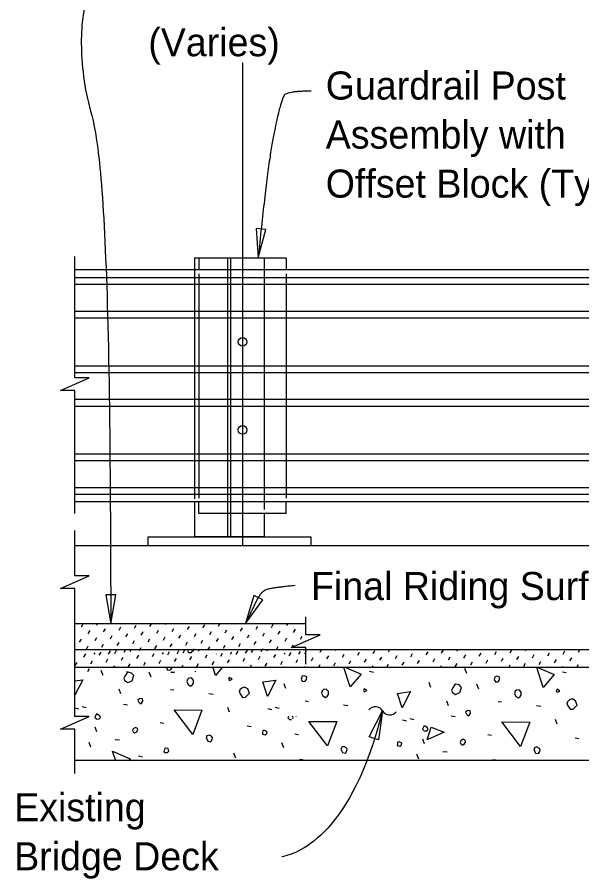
# Model space of a CAD drawing. Extents: x 21526.6 to 21598.7, y 56118.9 to 56155.9.
# Drawn here: x 21526.83 to 21530.88, y 56132.82 to 56139 of the extents above; entities that cross this region are included whole.
import ezdxf

# ---------------------------------------------------------------- set-up
doc = ezdxf.new("R2010")
doc.units = 0
for name, color, linetype in [('AdhocPoint_dp', 7, 'Continuous'), ('Border', 7, 'Continuous'), ('Patterning', 7, 'Continuous'), ('PlotBorder_dp', 7, 'Continuous'), ('SheetBorder_dp', 7, 'Continuous'), ('TextMisc', 7, 'Continuous')]:
    doc.layers.add(name, color=color, linetype=linetype)

msp = doc.modelspace()

# ---------------------------------------------------------------- linework, layer by layer
at = {"layer": 'AdhocPoint_dp'}
for p, q in [((21527.2426, 56135.21), (21535.6096, 56135.21)), ((21528.9006, 56134.6484), (21527.2426, 56134.6484)), ((21535.6096, 56134.46), (21527.2426, 56134.46)), ((21535.6096, 56134.335), (21527.2426, 56134.335)), ((21527.2426, 56133.6684), (21535.6096, 56133.6684))]:
    msp.add_line(p, q, dxfattribs=at)
at = {"layer": 'Patterning'}
for p, q in [((21528.4455, 56138.6758), (21528.4455, 56135.2123)), ((21528.758, 56137.2726), (21528.133, 56137.2726)), ((21528.133, 56137.2726), (21528.133, 56137.1892)), ((21528.758, 56137.2726), (21528.758, 56137.1892)), ((21528.133, 56137.1607), (21528.133, 56135.5488)), ((21528.758, 56137.1607), (21528.758, 56135.5488)), ((21527.2426, 56137.1336), (21534.2788, 56137.1336)), ((21527.2426, 56137.0854), (21534.2788, 56137.0854)), ((21527.2426, 56136.8926), (21534.2788, 56136.8926)), ((21527.2426, 56136.8444), (21534.2788, 56136.8444)), ((21527.2426, 56136.5004), (21534.2788, 56136.5004)), ((21527.2426, 56136.4522), (21534.2788, 56136.4522)), ((21527.2426, 56136.2594), (21534.2788, 56136.2594)), ((21527.2426, 56136.2112), (21534.2788, 56136.2112)), ((21527.2426, 56135.8673), (21534.2788, 56135.8673)), ((21527.2426, 56135.8191), (21534.2788, 56135.8191)), ((21527.2426, 56135.6262), (21534.2788, 56135.6262)), ((21527.2426, 56135.578), (21534.2788, 56135.578)), ((21528.133, 56135.4392), (21528.133, 56135.5226)), ((21528.758, 56135.4392), (21528.758, 56135.5226)), ((21528.758, 56135.4392), (21528.133, 56135.4392)), ((21527.2896, 56134.6259), (21527.3025, 56134.6483)), ((21527.4002, 56134.6388), (21527.4057, 56134.6484)), ((21527.449, 56134.59), (21527.462, 56134.6124)), ((21527.5597, 56134.603), (21527.5726, 56134.6254)), ((21527.6703, 56134.6159), (21527.6833, 56134.6383)), ((21527.7809, 56134.6289), (21527.7922, 56134.6484)), ((21527.8916, 56134.6419), (21527.8953, 56134.6484)), ((21527.9404, 56134.593), (21527.9534, 56134.6154)), ((21528.051, 56134.606), (21528.064, 56134.6284)), ((21528.1617, 56134.619), (21528.1746, 56134.6413)), ((21528.2723, 56134.6319), (21528.2818, 56134.6484)), ((21528.3829, 56134.6449), (21528.3849, 56134.6484)), ((21528.4318, 56134.596), (21528.4447, 56134.6184)), ((21528.5424, 56134.609), (21528.5553, 56134.6314)), ((21528.653, 56134.622), (21528.666, 56134.6444)), ((21528.7637, 56134.6349), (21528.7714, 56134.6484)), ((21528.8125, 56134.5861), (21528.8254, 56134.6085)), ((21528.8743, 56134.6479), (21528.8745, 56134.6484)), ((21527.3384, 56134.577), (21527.3514, 56134.5994)), ((21527.3872, 56134.5282), (21527.4002, 56134.5506)), ((21527.4979, 56134.5412), (21527.5108, 56134.5636)), ((21527.6085, 56134.5541), (21527.6215, 56134.5765)), ((21527.7191, 56134.5671), (21527.7321, 56134.5895)), ((21527.8298, 56134.5801), (21527.8427, 56134.6025)), ((21527.8786, 56134.5312), (21527.8916, 56134.5536)), ((21527.9892, 56134.5442), (21528.0022, 56134.5666)), ((21528.0999, 56134.5572), (21528.1128, 56134.5795)), ((21528.2105, 56134.5701), (21528.2235, 56134.5925)), ((21528.3211, 56134.5831), (21528.3341, 56134.6055)), ((21528.37, 56134.5342), (21528.3829, 56134.5566)), ((21528.4806, 56134.5472), (21528.4936, 56134.5696)), ((21528.5912, 56134.5602), (21528.6042, 56134.5826)), ((21528.7019, 56134.5731), (21528.7148, 56134.5955)), ((21528.7507, 56134.5243), (21528.7637, 56134.5467)), ((21528.8613, 56134.5373), (21528.8743, 56134.5597)), ((21527.2766, 56134.5152), (21527.2896, 56134.5376)), ((21527.3254, 56134.4664), (21527.3384, 56134.4888)), ((21527.4361, 56134.4794), (21527.449, 56134.5018)), ((21527.5467, 56134.4923), (21527.5597, 56134.5147)), ((21527.6573, 56134.5053), (21527.6703, 56134.5277)), ((21527.768, 56134.5183), (21527.7809, 56134.5407)), ((21527.8168, 56134.4694), (21527.8298, 56134.4918)), ((21527.9274, 56134.4824), (21527.9404, 56134.5048)), ((21528.0381, 56134.4954), (21528.051, 56134.5177)), ((21528.1487, 56134.5083), (21528.1617, 56134.5307)), ((21528.2593, 56134.5213), (21528.2723, 56134.5437)), ((21528.3082, 56134.4724), (21528.3211, 56134.4948)), ((21528.4188, 56134.4854), (21528.4318, 56134.5078)), ((21528.5294, 56134.4984), (21528.5424, 56134.5208)), ((21528.6401, 56134.5113), (21528.653, 56134.5337)), ((21528.6889, 56134.4625), (21528.7019, 56134.4849)), ((21528.7995, 56134.4755), (21528.8125, 56134.4979)), ((21528.9102, 56134.4884), (21528.9103, 56134.4886)), ((21527.2583, 56134.4585), (21527.2592, 56134.46)), ((21527.3071, 56134.4097), (21527.3201, 56134.4321)), ((21527.3811, 56134.4294), (21527.3872, 56134.44)), ((21527.4178, 56134.4226), (21527.4307, 56134.445)), ((21527.4849, 56134.4305), (21527.4979, 56134.4529)), ((21527.5284, 56134.4356), (21527.5413, 56134.458)), ((21527.5955, 56134.4435), (21527.6085, 56134.4659)), ((21527.639, 56134.4486), (21527.6457, 56134.46)), ((21527.6879, 56134.3997), (21527.7008, 56134.4221)), ((21527.7062, 56134.4565), (21527.7191, 56134.4789)), ((21527.7676, 56134.4294), (21527.768, 56134.43)), ((21527.7985, 56134.4127), (21527.8114, 56134.4351)), ((21527.8707, 56134.4294), (21527.8786, 56134.443)), ((21527.9091, 56134.4257), (21527.9221, 56134.4481)), ((21527.9763, 56134.4336), (21527.9892, 56134.4559)), ((21528.0198, 56134.4386), (21528.0321, 56134.46)), ((21528.0869, 56134.4465), (21528.0999, 56134.4689)), ((21528.1304, 56134.4516), (21528.1353, 56134.46)), ((21528.1792, 56134.4028), (21528.1922, 56134.4251)), ((21528.1975, 56134.4595), (21528.2105, 56134.4819)), ((21528.2572, 56134.4294), (21528.2593, 56134.433)), ((21528.2899, 56134.4157), (21528.3028, 56134.4381)), ((21528.3603, 56134.4294), (21528.37, 56134.446)), ((21528.4005, 56134.4287), (21528.4134, 56134.4511)), ((21528.4676, 56134.4366), (21528.4806, 56134.459)), ((21528.5111, 56134.4416), (21528.5218, 56134.46)), ((21528.5783, 56134.4495), (21528.5912, 56134.4719)), ((21528.6217, 56134.4546), (21528.6249, 56134.46)), ((21528.6706, 56134.4058), (21528.6835, 56134.4282)), ((21528.7468, 56134.4294), (21528.7507, 56134.4361)), ((21528.7812, 56134.4187), (21528.7942, 56134.4411)), ((21528.8499, 56134.4294), (21528.8613, 56134.449)), ((21528.8918, 56134.4317), (21528.9048, 56134.4541)), ((21529.0025, 56134.4447), (21529.0114, 56134.46)), ((21529.1131, 56134.4576), (21529.1145, 56134.46)), ((21529.1619, 56134.4088), (21529.1749, 56134.4312)), ((21529.2726, 56134.4218), (21529.2855, 56134.4441)), ((21529.3832, 56134.4347), (21529.3962, 56134.4571)), ((21529.4938, 56134.4477), (21529.501, 56134.46)), ((21529.6533, 56134.4118), (21529.6663, 56134.4342)), ((21529.7639, 56134.4248), (21529.7769, 56134.4472)), ((21529.8746, 56134.4377), (21529.8875, 56134.46)), ((21529.9852, 56134.4507), (21529.9906, 56134.46)), ((21530.034, 56134.4019), (21530.047, 56134.4243)), ((21530.1447, 56134.4148), (21530.1576, 56134.4372)), ((21530.2553, 56134.4278), (21530.2683, 56134.4502)), ((21530.3659, 56134.4408), (21530.3771, 56134.46)), ((21530.4766, 56134.4537), (21530.4802, 56134.46)), ((21530.5254, 56134.4049), (21530.5384, 56134.4273)), ((21530.636, 56134.4179), (21530.649, 56134.4402)), ((21530.7467, 56134.4308), (21530.7596, 56134.4532)), ((21530.8573, 56134.4438), (21530.8667, 56134.46)), ((21527.2453, 56134.3479), (21527.2583, 56134.3703)), ((21527.356, 56134.3608), (21527.3689, 56134.3832)), ((21527.4666, 56134.3738), (21527.4796, 56134.3962)), ((21527.5772, 56134.3868), (21527.5902, 56134.4092)), ((21527.6261, 56134.3379), (21527.639, 56134.3603)), ((21527.7367, 56134.3509), (21527.7497, 56134.3733)), ((21527.8473, 56134.3639), (21527.8603, 56134.3863)), ((21527.958, 56134.3768), (21527.9709, 56134.3992)), ((21528.0686, 56134.3898), (21528.0815, 56134.4122)), ((21528.1174, 56134.341), (21528.1304, 56134.3633)), ((21528.2281, 56134.3539), (21528.241, 56134.3763)), ((21528.3387, 56134.3669), (21528.3516, 56134.3893)), ((21528.4493, 56134.3798), (21528.4623, 56134.4022)), ((21528.56, 56134.3928), (21528.5729, 56134.4152)), ((21528.6088, 56134.344), (21528.6217, 56134.3664)), ((21528.7194, 56134.3569), (21528.7324, 56134.3793)), ((21528.8301, 56134.3699), (21528.843, 56134.3923)), ((21528.9407, 56134.3829), (21528.9536, 56134.4053)), ((21529.0513, 56134.3958), (21529.0643, 56134.4182)), ((21529.1002, 56134.347), (21529.1131, 56134.3694)), ((21529.2108, 56134.36), (21529.2237, 56134.3824)), ((21529.3214, 56134.3729), (21529.3344, 56134.3953)), ((21529.432, 56134.3859), (21529.445, 56134.4083)), ((21529.5427, 56134.3989), (21529.5556, 56134.4212)), ((21529.5915, 56134.35), (21529.6045, 56134.3724)), ((21529.7021, 56134.363), (21529.7151, 56134.3854)), ((21529.8128, 56134.3759), (21529.8257, 56134.3983)), ((21529.9234, 56134.3889), (21529.9364, 56134.4113)), ((21529.9722, 56134.3401), (21529.9852, 56134.3625)), ((21530.0829, 56134.353), (21530.0958, 56134.3754)), ((21530.1935, 56134.366), (21530.2065, 56134.3884)), ((21530.3041, 56134.379), (21530.3171, 56134.4014)), ((21530.4148, 56134.3919), (21530.4277, 56134.4143)), ((21530.4636, 56134.3431), (21530.4766, 56134.3655)), ((21530.5742, 56134.3561), (21530.5872, 56134.3784)), ((21530.6849, 56134.369), (21530.6978, 56134.3914)), ((21530.7955, 56134.382), (21530.8085, 56134.4044)), ((21527.3349, 56134.3055), (21527.3478, 56134.3279)), ((21527.4465, 56134.2767), (21527.4324, 56134.3121)), ((21527.5212, 56134.335), (21527.5284, 56134.3474)), ((21527.6176, 56134.3044), (21527.6179, 56134.305)), ((21527.7906, 56134.265), (21527.7765, 56134.3003)), ((21527.9077, 56134.335), (21527.9091, 56134.3374)), ((21528.0109, 56134.335), (21528.0198, 56134.3504)), ((21528.1072, 56134.3044), (21528.1093, 56134.308)), ((21528.3974, 56134.335), (21528.4005, 56134.3404)), ((21528.5005, 56134.335), (21528.5111, 56134.3534)), ((21528.887, 56134.335), (21528.8918, 56134.3435)), ((21528.9901, 56134.335), (21529.0025, 56134.3564)), ((21529.3562, 56134.3079), (21529.3845, 56134.3008)), ((21529.3766, 56134.335), (21529.3832, 56134.3465)), ((21529.4809, 56134.3371), (21529.4938, 56134.3594)), ((21529.7631, 56134.335), (21529.7639, 56134.3365)), ((21529.8662, 56134.335), (21529.8746, 56134.3495)), ((21530.0545, 56134.292), (21530.0403, 56134.3273)), ((21530.2527, 56134.335), (21530.2553, 56134.3396)), ((21530.3558, 56134.335), (21530.3659, 56134.3525)), ((21530.7409, 56134.3043), (21530.7691, 56134.2973)), ((21530.7423, 56134.335), (21530.7467, 56134.3426)), ((21530.8454, 56134.335), (21530.8573, 56134.3555)), ((21527.572, 56134.1442), (21527.5597, 56134.1777)), ((21527.9285, 56134.1766), (21527.9533, 56134.1731)), ((21528.7575, 56134.183), (21528.7434, 56134.2183)), ((21529.7981, 56134.1912), (21529.784, 56134.2266)), ((21530.1422, 56134.1795), (21530.1281, 56134.2148)), ((21528.2043, 56134.1483), (21528.2343, 56134.143)), ((21527.2945, 56134.054), (21527.3228, 56134.0469)), ((21527.5909, 56134.0723), (21527.6209, 56134.067)), ((21528.8954, 56134.0946), (21528.9202, 56134.0911)), ((21529.1712, 56134.0663), (21529.2012, 56134.061)), ((21529.9236, 56134.0586), (21529.9113, 56134.0922)), ((21530.2801, 56134.0911), (21530.3049, 56134.0875)), ((21530.5559, 56134.0628), (21530.5859, 56134.0575)), ((21527.2421, 56134.044), (21527.2704, 56134.037)), ((21528.3528, 56134.014), (21528.3404, 56134.0476)), ((21528.6268, 56134.0405), (21528.6551, 56134.0334)), ((21528.6792, 56134.0505), (21528.7075, 56134.0434)), ((21527.8543, 56133.9397), (21527.8808, 56133.9344)), ((21529.5937, 56133.9585), (21529.622, 56133.9514)), ((21529.6461, 56133.9685), (21529.6744, 56133.9614)), ((21529.9425, 56133.9868), (21529.9725, 56133.9815)), ((21530.7044, 56133.9284), (21530.692, 56133.962)), ((21527.4006, 56133.8714), (21527.3882, 56133.905)), ((21528.48, 56133.915), (21528.5066, 56133.9097)), ((21527.5308, 56133.8177), (21527.5626, 56133.8142)), ((21528.8212, 56133.8577), (21528.8477, 56133.8524)), ((21529.7522, 56133.7859), (21529.7398, 56133.8195)), ((21530.2059, 56133.8542), (21530.2324, 56133.8489)), ((21530.8316, 56133.8294), (21530.8582, 56133.8241)), ((21527.3581, 56133.7618), (21527.344, 56133.7972)), ((21528.7428, 56133.7583), (21528.7287, 56133.7936)), ((21527.6987, 56133.6993), (21527.727, 56133.6922)), ((21528.397, 56133.6834), (21528.3828, 56133.7188)), ((21529.7097, 56133.6763), (21529.6956, 56133.7116)), ((21529.8824, 56133.7322), (21529.9142, 56133.7287))]:
    msp.add_line(p, q, dxfattribs=at)
for points in [[(21528.0505, 56134.4567), (21528.0591, 56134.4413), (21528.0785, 56134.443), (21528.0874, 56134.4554), (21528.0875, 56134.4567)], [(21527.6003, 56134.2396), (21527.6233, 56134.2272), (21527.6534, 56134.2396), (21527.6657, 56134.2767), (21527.6481, 56134.2944), (21527.6251, 56134.2997), (21527.6145, 56134.2927), (21527.6021, 56134.2732), (21527.5933, 56134.2573), (21527.6003, 56134.2396)], [(21527.9005, 56134.3317), (21527.9091, 56134.3163), (21527.9285, 56134.318), (21527.9373, 56134.3304), (21527.9375, 56134.3317)], [(21527.9326, 56134.3044), (21527.9336, 56134.302), (21527.9312, 56134.3044)], [(21527.9336, 56134.302), (21527.9548, 56134.302), (21527.9572, 56134.3044)], [(21528.252, 56134.2774), (21528.2343, 56134.3317)], [(21528.298, 56134.3317), (21528.252, 56134.2774)], [(21529.2189, 56134.1954), (21529.1735, 56134.335)], [(21529.1874, 56134.335), (21529.2967, 56134.2873), (21529.2189, 56134.1954)], [(21530.6036, 56134.1918), (21530.557, 56134.335)], [(21530.564, 56134.335), (21530.6814, 56134.2838), (21530.6036, 56134.1918)], [(21527.2426, 56134.2391), (21527.2998, 56134.2467), (21527.2427, 56134.1358)], [(21528.0452, 56134.2332), (21528.0558, 56134.212), (21528.0735, 56134.2014), (21528.0876, 56134.212), (21528.0947, 56134.2226), (21528.0947, 56134.2438), (21528.0788, 56134.2597), (21528.0593, 56134.2579), (21528.0505, 56134.2491), (21528.0452, 56134.2332)], [(21528.351, 56134.242), (21528.3704, 56134.2509), (21528.3634, 56134.2579), (21528.351, 56134.2632), (21528.3457, 56134.2509), (21528.351, 56134.242)], [(21528.6244, 56134.1265), (21528.5908, 56134.2308), (21528.6845, 56134.2432), (21528.6244, 56134.1265)], [(21528.8671, 56134.2502), (21528.876, 56134.2343), (21528.8954, 56134.236), (21528.9043, 56134.2484), (21528.906, 56134.2678), (21528.8937, 56134.2731), (21528.8848, 56134.2749), (21528.8742, 56134.2714), (21528.8707, 56134.2678), (21528.8671, 56134.2502)], [(21530.2518, 56134.2466), (21530.2607, 56134.2307), (21530.2801, 56134.2325), (21530.2889, 56134.2449), (21530.2907, 56134.2643), (21530.2783, 56134.2696), (21530.2695, 56134.2714), (21530.2589, 56134.2678), (21530.2554, 56134.2643), (21530.2518, 56134.2466)], [(21528.4217, 56134.1572), (21528.4447, 56134.12), (21528.4677, 56134.1218), (21528.4765, 56134.1306), (21528.496, 56134.1501), (21528.4836, 56134.1801), (21528.4588, 56134.1943), (21528.4412, 56134.1872), (21528.427, 56134.1731), (21528.4217, 56134.1572)], [(21529.0121, 56134.1512), (21529.0227, 56134.13), (21529.0404, 56134.1194), (21529.0545, 56134.13), (21529.0616, 56134.1406), (21529.0616, 56134.1618), (21529.0457, 56134.1777), (21529.0262, 56134.1759), (21529.0174, 56134.1671), (21529.0121, 56134.1512)], [(21529.3179, 56134.16), (21529.3374, 56134.1689), (21529.3303, 56134.1759), (21529.3179, 56134.1812), (21529.3126, 56134.1689), (21529.3179, 56134.16)], [(21529.9519, 56134.1541), (21529.9749, 56134.1417), (21530.005, 56134.1541), (21530.0173, 56134.1912), (21529.9997, 56134.2089), (21529.9767, 56134.2142), (21529.9661, 56134.2071), (21529.9537, 56134.1877), (21529.9449, 56134.1718), (21529.9519, 56134.1541)], [(21530.7026, 56134.1565), (21530.722, 56134.1653), (21530.715, 56134.1724), (21530.7026, 56134.1777), (21530.6973, 56134.1653), (21530.7026, 56134.1565)], [(21529.5913, 56134.0445), (21529.5577, 56134.1488), (21529.6514, 56134.1612), (21529.5913, 56134.0445)], [(21530.3968, 56134.1476), (21530.4074, 56134.1264), (21530.4251, 56134.1158), (21530.4392, 56134.1264), (21530.4463, 56134.137), (21530.4463, 56134.1582), (21530.4304, 56134.1742), (21530.4109, 56134.1724), (21530.4021, 56134.1635), (21530.3968, 56134.1476)], [(21527.7022, 56134.0847), (21527.7128, 56134.0741), (21527.7234, 56134.0811), (21527.7305, 56134.0918), (21527.727, 56134.1094), (21527.7181, 56134.1112), (21527.7058, 56134.1094), (21527.6952, 56134.0988), (21527.7022, 56134.0847)], [(21530.7733, 56134.0716), (21530.7963, 56134.0345), (21530.8193, 56134.0363), (21530.8281, 56134.0451), (21530.8476, 56134.0646), (21530.8352, 56134.0946), (21530.8104, 56134.1087), (21530.7928, 56134.1017), (21530.7786, 56134.0875), (21530.7733, 56134.0716)], [(21527.397, 56133.9656), (21527.4094, 56133.9638), (21527.4218, 56133.9692), (21527.4253, 56133.9798), (21527.42, 56133.9886), (21527.4094, 56133.9957), (21527.397, 56134.001), (21527.39, 56133.9868), (21527.3864, 56133.9762), (21527.397, 56133.9656)], [(21528.0894, 56133.8531), (21527.955, 56134.0299), (21528.1548, 56134.0281), (21528.0894, 56133.8531)], [(21530.0538, 56133.9991), (21530.0644, 56133.9885), (21530.075, 56133.9956), (21530.0821, 56134.0062), (21530.0786, 56134.0239), (21530.0697, 56134.0257), (21530.0574, 56134.0239), (21530.0468, 56134.0133), (21530.0538, 56133.9991)], [(21528.776, 56133.9861), (21528.7746, 56133.9833), (21528.7711, 56133.9727), (21528.7817, 56133.9621)], [(21528.7817, 56133.9621), (21528.7941, 56133.9603), (21528.796, 56133.9611)], [(21528.8073, 56133.9681), (21528.81, 56133.9762), (21528.8047, 56133.9851), (21528.8031, 56133.9861)], [(21528.8302, 56133.9823), (21528.8314, 56133.9861)], [(21529.0563, 56133.7711), (21528.9219, 56133.9479), (21529.1217, 56133.9461), (21529.0563, 56133.7711)], [(21530.441, 56133.7676), (21530.3066, 56133.9443), (21530.5064, 56133.9426), (21530.441, 56133.7676)], [(21527.6669, 56133.8655), (21527.6739, 56133.8655), (21527.6881, 56133.8725), (21527.6934, 56133.8885), (21527.6916, 56133.8973), (21527.6775, 56133.9044), (21527.6598, 56133.8938), (21527.6563, 56133.8832), (21527.6598, 56133.8725), (21527.6669, 56133.8655)], [(21528.5879, 56133.8566), (21528.6073, 56133.8513), (21528.6197, 56133.8602), (21528.6215, 56133.8725), (21528.6179, 56133.8761), (21528.6038, 56133.8832), (21528.5914, 56133.8814), (21528.5897, 56133.869), (21528.5879, 56133.8566)], [(21529.7486, 56133.8801), (21529.761, 56133.8783), (21529.7734, 56133.8836), (21529.7769, 56133.8942), (21529.7716, 56133.9031), (21529.761, 56133.9101), (21529.7486, 56133.9154), (21529.7416, 56133.9013), (21529.738, 56133.8907), (21529.7486, 56133.8801)], [(21529.771, 56133.8153), (21529.7993, 56133.9072), (21529.893, 56133.8701), (21529.771, 56133.8153)], [(21528.1884, 56133.8213), (21528.1972, 56133.8054), (21528.2184, 56133.8018), (21528.2273, 56133.8177), (21528.2308, 56133.8319), (21528.222, 56133.8407), (21528.206, 56133.8496), (21528.1901, 56133.8443), (21528.1848, 56133.8284), (21528.1884, 56133.8213)], [(21530.0185, 56133.7799), (21530.0255, 56133.7799), (21530.0397, 56133.787), (21530.045, 56133.8029), (21530.0432, 56133.8118), (21530.0291, 56133.8188), (21530.0114, 56133.8082), (21530.0079, 56133.7976), (21530.0114, 56133.787), (21530.0185, 56133.7799)], [(21527.8861, 56133.7241), (21527.9073, 56133.7241), (21527.9179, 56133.7347), (21527.9126, 56133.7541), (21527.8896, 56133.7559), (21527.8861, 56133.7453), (21527.8808, 56133.7364), (21527.8861, 56133.7241), (21527.8825, 56133.7276)], [(21529.1553, 56133.7393), (21529.1641, 56133.7234), (21529.1853, 56133.7198), (21529.1942, 56133.7357), (21529.1977, 56133.7499), (21529.1889, 56133.7587), (21529.173, 56133.7676), (21529.1571, 56133.7623), (21529.1518, 56133.7464), (21529.1553, 56133.7393)], [(21529.5548, 56133.7746), (21529.5742, 56133.7693), (21529.5866, 56133.7782), (21529.5884, 56133.7905), (21529.5849, 56133.7941), (21529.5707, 56133.8012), (21529.5583, 56133.7994), (21529.5566, 56133.787), (21529.5548, 56133.7746)], [(21530.54, 56133.7357), (21530.5488, 56133.7198), (21530.57, 56133.7163), (21530.5789, 56133.7322), (21530.5824, 56133.7464), (21530.5736, 56133.7552), (21530.5576, 56133.764), (21530.5417, 56133.7587), (21530.5364, 56133.7428), (21530.54, 56133.7357)], [(21527.536, 56133.665), (21527.5137, 56133.7335), (21527.6392, 56133.6787), (21527.6276, 56133.665)], [(21528.8805, 56133.6684), (21528.8795, 56133.6721), (21528.8565, 56133.6739), (21528.8547, 56133.6684)], [(21530.2643, 56133.6684), (21530.2642, 56133.6686), (21530.2412, 56133.6703), (21530.2406, 56133.6684)]]:
    msp.add_lwpolyline(points, dxfattribs=at)
at = {"layer": 'PlotBorder_dp'}
for points in [[(21528.5583, 56137.2748), (21528.614, 56137.4786), (21528.5438, 56137.4856)], [(21527.5005, 56134.6471), (21527.5357, 56134.8553), (21527.4652, 56134.8553)], [(21528.466, 56134.6497), (21528.5907, 56134.8202), (21528.5275, 56134.8517)], [(21529.4513, 56134.0231), (21529.4208, 56133.8141), (21529.3537, 56133.8358)]]:
    msp.add_lwpolyline(points, close=True, dxfattribs=at)
for points in [[(21527.2427, 56135.4395), (21527.2427, 56136.3228), (21527.1393, 56136.3228), (21527.2427, 56136.3678), (21527.346, 56136.4128), (21527.2427, 56136.4128), (21527.2427, 56137.2857)], [(21527.2427, 56134.3351), (21527.2427, 56134.9021), (21527.1393, 56134.9021), (21527.2427, 56134.9471), (21527.346, 56134.9921), (21527.2427, 56134.9921), (21527.2427, 56135.3182)], [(21528.9006, 56134.3576), (21528.9006, 56134.4784), (21528.7973, 56134.4784), (21528.9006, 56134.5234), (21529.004, 56134.5684), (21528.9006, 56134.5684), (21528.9006, 56134.699)], [(21527.2427, 56133.5727), (21527.2427, 56133.8927), (21527.1393, 56133.8927), (21527.2427, 56133.9377), (21527.346, 56133.9827), (21527.2427, 56133.9827), (21527.2427, 56134.3351)]]:
    msp.add_lwpolyline(points, dxfattribs=at)
for centre, start, end in [((21529.3989, 56133.9934), 30.00813, 141.73535), ((21529.5022, 56134.053), 210.00813, 321.73535)]:
    msp.add_arc(centre, 0.0596, start, end, dxfattribs=at)
for points, degree in [([(21527.6956, 56139.5056), (21527.5358, 56139.5261), (21527.352, 56139.3409), (21527.253, 56138.6974), (21527.5005, 56137.7639), (21527.5005, 56134.6471)], 2), ([(21528.9375, 56138.4713), (21528.774, 56138.4713), (21528.7217, 56138.419), (21528.6236, 56137.9315), (21528.5583, 56137.2748)], 2), ([(21528.8223, 56134.922), (21528.6486, 56134.9066), (21528.5744, 56134.8752), (21528.5088, 56134.7353), (21528.466, 56134.6497)], 2), ([(21529.4505, 56134.0233), (21529.2298, 56133.1495), (21528.8638, 56133.0022), (21528.727, 56132.9754)], 3)]:
    msp.add_open_spline(points, degree=degree, dxfattribs=at)
at = {"layer": 'SheetBorder_dp'}
for p, q in [((21528.1017, 56137.2726), (21528.1017, 56135.5456)), ((21528.3413, 56135.2726), (21528.3413, 56137.2726)), ((21528.3622, 56135.2726), (21528.3622, 56137.2726)), ((21528.6017, 56137.2726), (21528.6017, 56135.4691))]:
    msp.add_line(p, q, dxfattribs=at)
at = {"layer": 'TextMisc'}
for p, q in [((21528.6017, 56137.2726), (21528.1017, 56137.2726)), ((21534.2788, 56137.1892), (21527.2426, 56137.1892)), ((21534.2788, 56135.5225), (21527.2426, 56135.5225)), ((21528.1017, 56135.5225), (21528.1017, 56135.2726)), ((21528.6017, 56135.4392), (21528.6017, 56135.2726)), ((21527.7684, 56135.2726), (21528.9351, 56135.2726)), ((21527.7684, 56135.2101), (21527.7684, 56135.2726)), ((21528.6017, 56135.2726), (21528.1017, 56135.2726)), ((21528.9351, 56135.2726), (21528.9351, 56135.2101)), ((21527.7684, 56135.2101), (21528.9351, 56135.2101))]:
    msp.add_line(p, q, dxfattribs=at)
for centre in [(21528.4455, 56136.6725), (21528.4455, 56136.0393)]:
    msp.add_circle(centre, 0.0312, dxfattribs=at)

# ---------------------------------------------------------------- texts
at = {"layer": 'Border'}
msp.add_text('Final Riding Surface', height=0.2016, dxfattribs=at).set_placement((21528.9369, 56134.8183))
at = {"layer": 'PlotBorder_dp'}
for s, p in [('(Varies)', (21527.7694, 56138.7219)), ('Guardrail Post ', (21529.0427, 56138.4112)), ('Assembly with ', (21529.0427, 56138.0592)), ('Offset Block (Typ.)', (21529.0427, 56137.7072)), ('Existing ', (21526.8068, 56133.2307)), ('Bridge Deck', (21526.8068, 56132.8787))]:
    msp.add_text(s, height=0.2016, dxfattribs=at).set_placement(p)

doc.saveas('drawing.dxf')
